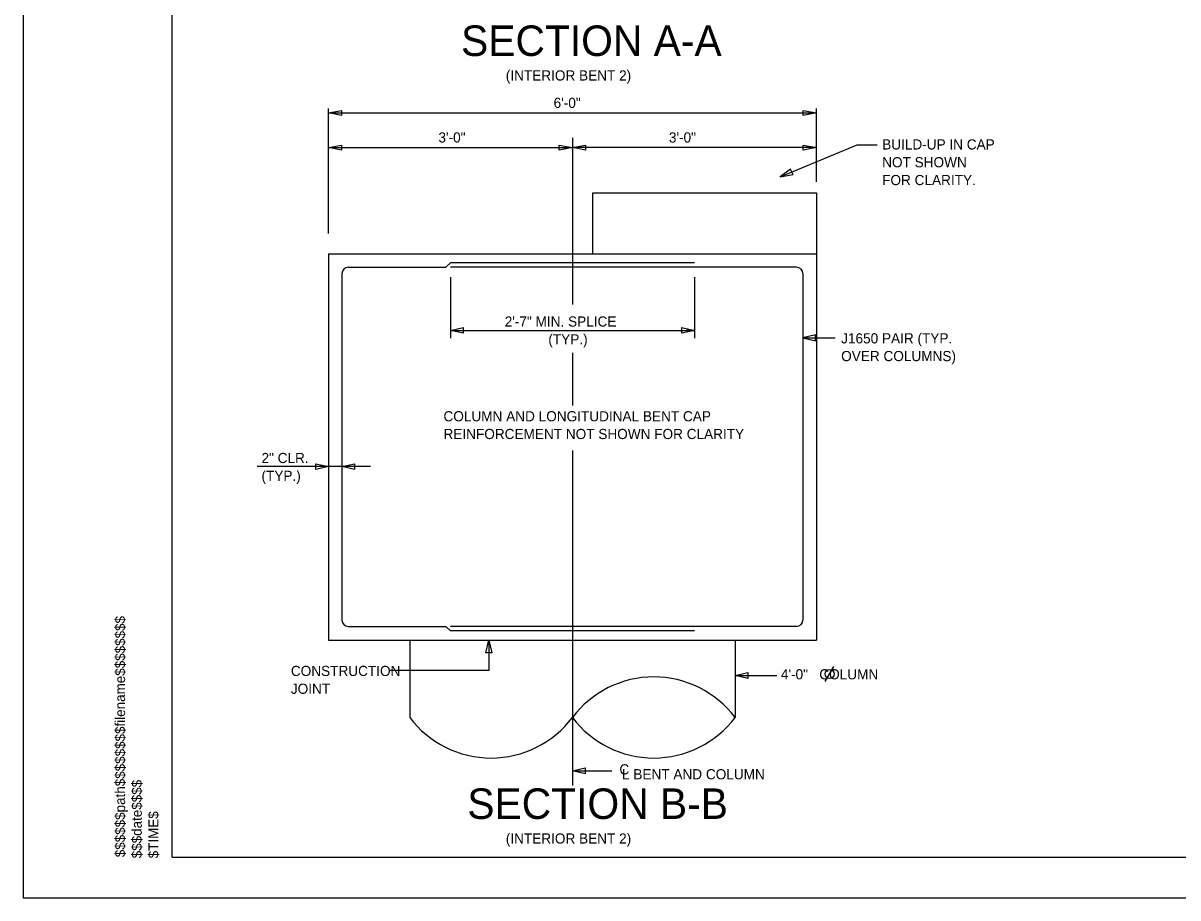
# Model space of a CAD drawing. Extents: x -133.1 to -97, y -1.7 to 20.3.
# Drawn here: x -133.14 to -118.94, y -1.69 to 9.06 of the extents above; entities that cross this region are included whole.
import ezdxf

# ---------------------------------------------------------------- set-up
doc = ezdxf.new("R2010")
doc.units = 0
for name, color, linetype in [('BR_AUTO DIMENSION', 7, 'Continuous'), ('BR_BORDER LINES', 7, 'Continuous'), ('BR_CENTER LINES', 7, 'Continuous'), ('BR_CONCRETE', 7, 'Continuous'), ('BR_REBAR', 7, 'Continuous'), ('BR_TEXT', 7, 'Continuous'), ('Level 31', 7, 'Continuous'), ('RD_SHT_ID', 7, 'Continuous')]:
    doc.layers.add(name, color=color, linetype=linetype)

msp = doc.modelspace()

# ---------------------------------------------------------------- linework, layer by layer
at = {"layer": 'BR_AUTO DIMENSION'}
for p, q in [((-129.388, 6.477), (-129.388, 8.016)), ((-129.388, 7.959), (-123.388, 7.959)), ((-123.388, 7.112), (-123.388, 8.016)), ((-129.388, 7.534), (-126.388, 7.534)), ((-123.388, 7.534), (-126.388, 7.534)), ((-123.832, 7.172), (-122.886, 7.568)), ((-122.886, 7.568), (-122.641, 7.568)), ((-127.888, 5.942), (-127.888, 5.189)), ((-124.888, 5.942), (-124.888, 5.189)), ((-127.888, 5.286), (-124.888, 5.286)), ((-123.555, 5.195), (-123.159, 5.195)), ((-128.87, 3.611), (-130.262, 3.611)), ((-127.415, 1.479), (-127.415, 1.106)), ((-127.415, 1.106), (-128.639, 1.106)), ((-124.388, 1.044), (-123.876, 1.044)), ((-126.388, -0.128), (-125.905, -0.128))]:
    msp.add_line(p, q, dxfattribs=at)
for points in [[(-129.226, 7.927), (-129.388, 7.959), (-129.226, 7.99)], [(-123.551, 7.99), (-123.388, 7.959), (-123.551, 7.927)], [(-129.226, 7.502), (-129.388, 7.534), (-129.226, 7.565)], [(-126.551, 7.565), (-126.388, 7.534), (-126.551, 7.502)], [(-126.226, 7.502), (-126.388, 7.534), (-126.226, 7.565)], [(-123.551, 7.565), (-123.388, 7.534), (-123.551, 7.502)], [(-123.705, 7.269), (-123.832, 7.172), (-123.675, 7.204)], [(-127.732, 5.25), (-127.888, 5.286), (-127.732, 5.322)], [(-125.044, 5.322), (-124.888, 5.286), (-125.044, 5.25)], [(-123.399, 5.231), (-123.555, 5.195), (-123.399, 5.159)], [(-129.544, 3.647), (-129.388, 3.611), (-129.544, 3.575)], [(-129.065, 3.575), (-129.221, 3.611), (-129.065, 3.647)], [(-127.451, 1.323), (-127.415, 1.479), (-127.379, 1.323)], [(-124.232, 1.008), (-124.388, 1.044), (-124.232, 1.08)], [(-126.232, -0.164), (-126.388, -0.128), (-126.232, -0.092)]]:
    msp.add_lwpolyline(points, close=True, dxfattribs=at)
at = {"layer": 'BR_BORDER LINES'}
for q in [(-131.308, 19.809), (-97.642, -1.191)]:
    msp.add_line((-131.308, -1.191), q, dxfattribs=at)
at = {"layer": 'BR_CENTER LINES'}
for p, q in [((-126.388, 7.655), (-126.388, 5.605)), ((-126.388, 5.011), (-126.388, 4.363)), ((-126.388, 3.808), (-126.388, -0.307))]:
    msp.add_line(p, q, dxfattribs=at)
at = {"layer": 'BR_CONCRETE'}
for p, q in [((-126.138, 6.229), (-126.138, 6.979)), ((-126.138, 6.979), (-123.388, 6.979)), ((-123.388, 6.979), (-123.388, 1.479)), ((-129.388, 6.229), (-129.388, 1.479)), ((-129.388, 6.229), (-123.388, 6.229)), ((-129.388, 1.479), (-128.388, 1.479)), ((-128.388, 1.479), (-128.388, 0.528)), ((-128.388, 1.479), (-124.388, 1.479)), ((-124.388, 1.479), (-123.388, 1.479)), ((-124.388, 1.479), (-124.388, 0.528))]:
    msp.add_line(p, q, dxfattribs=at)
for centre, start, end in [((-125.388, -0.226), 37.0023, 142.9977), ((-127.388, 1.281), 217.0023, 322.9977), ((-125.388, 1.281), 217.0023, 322.9977)]:
    msp.add_arc(centre, 1.252, start, end, dxfattribs=at)
at = {"layer": 'BR_REBAR'}
for p, q in [((-127.943, 6.063), (-127.888, 6.118)), ((-124.888, 6.118), (-127.888, 6.118)), ((-129.221, 5.985), (-129.221, 1.724)), ((-129.143, 6.063), (-127.943, 6.063)), ((-123.633, 6.063), (-127.888, 6.063)), ((-123.555, 5.985), (-123.555, 1.724)), ((-129.143, 1.646), (-127.944, 1.646)), ((-127.944, 1.646), (-127.888, 1.591)), ((-123.63, 1.646), (-127.888, 1.646)), ((-124.888, 1.591), (-127.888, 1.591))]:
    msp.add_line(p, q, dxfattribs=at)
for centre, start, end in [((-129.143, 5.985), 90, 180), ((-123.633, 5.985), 360, 90), ((-129.143, 1.724), 180, 270), ((-123.633, 1.724), 270, 360)]:
    msp.add_arc(centre, 0.0781, start, end, dxfattribs=at)
at = {"layer": 'BR_TEXT'}
for p, q in [((-127.888, 5.286), (-127.811, 5.286)), ((-124.888, 5.286), (-124.985, 5.286)), ((-123.279, 0.971), (-123.174, 1.153))]:
    msp.add_line(p, q, dxfattribs=at)
msp.add_circle((-123.226, 1.062), 0.055, dxfattribs=at)
at = {"layer": 'Level 31'}
msp.add_lwpolyline([(-133.141, -1.691), (-97.141, -1.691), (-97.141, 20.309), (-133.141, 20.309)], close=True, dxfattribs=at)

# ---------------------------------------------------------------- texts
at = {"layer": 'BR_AUTO DIMENSION'}
for s, p in [('6\'-0"', (-126.619, 8.021)), ('3\'-0"', (-128.035, 7.596)), ('3\'-0"', (-125.202, 7.596))]:
    msp.add_text(s, height=0.125, dxfattribs=at).set_placement(p)
at = {"layer": 'BR_TEXT'}
for s, p in [('SECTION A-A', (-127.757, 8.66)), ('SECTION B-B', (-127.68, -0.72))]:
    msp.add_text(s, height=0.375, dxfattribs=at).set_placement(p)
for s, p in [('(INTERIOR BENT 2)', (-127.207, 8.358)), ('BUILD-UP IN CAP', (-122.58, 7.51)), ('NOT SHOWN', (-122.58, 7.291)), ('FOR CLARITY.', (-122.58, 7.072)), ('2\'-7" MIN. SPLICE', (-127.22, 5.333)), ('J1650 PAIR (TYP.', (-123.084, 5.126)), ('(TYP.)', (-126.684, 5.114)), ('OVER COLUMNS)', (-123.084, 4.908)), ('COLUMN AND LONGITUDINAL BENT CAP', (-127.973, 4.168)), ('REINFORCEMENT NOT SHOWN FOR CLARITY', (-127.973, 3.95)), ('2" CLR.', (-130.21, 3.655)), ('(TYP.)', (-130.21, 3.436)), ('CONSTRUCTION', (-129.849, 1.037)), ('4\'-0"   COLUMN', (-123.825, 0.996)), ('JOINT', (-129.849, 0.818)), ('C', (-125.81, -0.173)), ('L BENT AND COLUMN', (-125.778, -0.233)), ('(INTERIOR BENT 2)', (-127.207, -1.023))]:
    msp.add_text(s, height=0.125, rotation=360, dxfattribs=at).set_placement(p)
at = {"layer": 'RD_SHT_ID'}
for s, height, p in [('$$$$$$path$$$$$$$$filename$$$$$$$$', 0.12347, (-131.887, -1.191)), ('$$$date$$$$', 0.12347, (-131.682, -1.204)), ('$TIME$', 0.1235, (-131.477, -1.204))]:
    msp.add_text(s, height=height, rotation=90, dxfattribs=at).set_placement(p)

doc.saveas('drawing.dxf')
